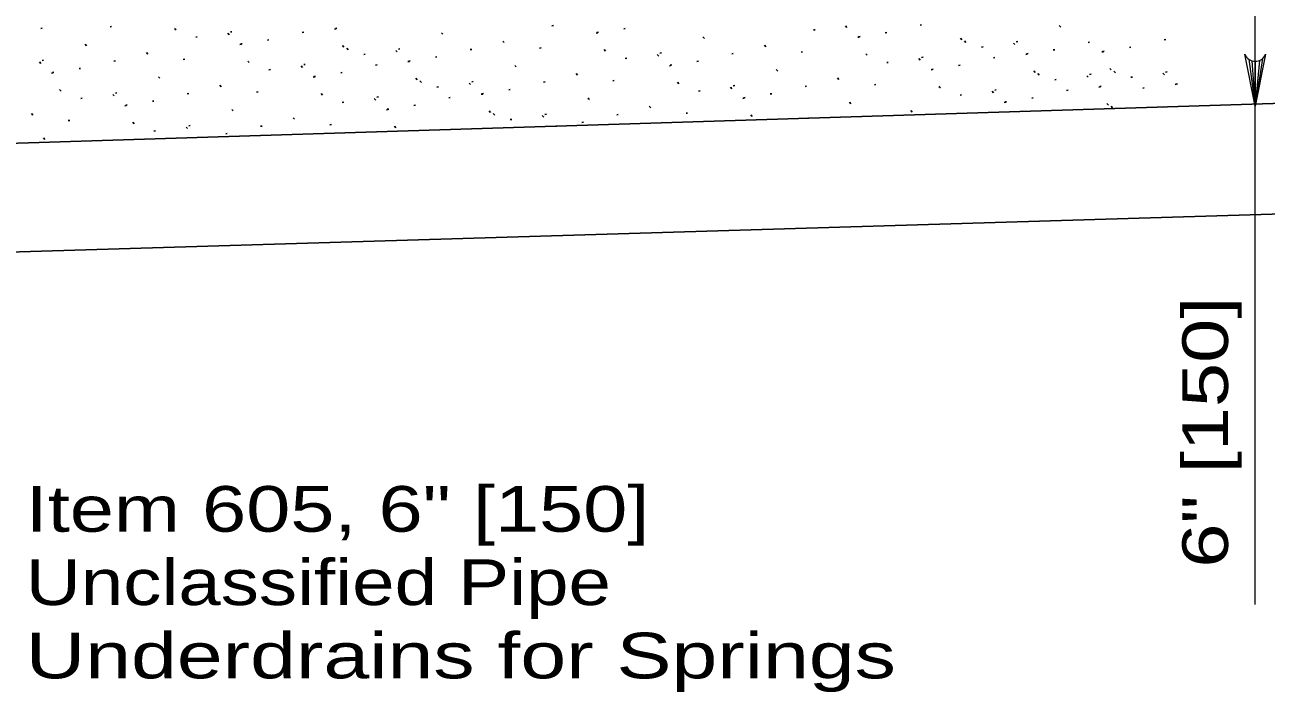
# Model space of a CAD drawing. Extents: x 1083.1 to 1117.1, y 697.4 to 741.4.
# Drawn here: x 1093.807 to 1098.05, y 702.6 to 704.879 of the extents above; entities that cross this region are included whole.
import ezdxf
from ezdxf.enums import TextEntityAlignment as Align

# ---------------------------------------------------------------- set-up
doc = ezdxf.new("R2010")
doc.units = 0
doc.header["$LTSCALE"] = 0.062
doc.layers.add('1', color=7, linetype='Continuous', lineweight=13)

msp = doc.modelspace()

# ---------------------------------------------------------------- linework, layer by layer
at = {"layer": '1'}
for p, q in [((1098.0125, 702.899), (1098.0125, 707.79508)), ((1097.99008, 704.76167), (1098.0125, 704.60142)), ((1098.00117, 704.75625), (1098.0125, 704.60142)), ((1098.03733, 704.76358), (1098.0125, 704.60142)), ((1098.02692, 704.75742), (1098.0125, 704.60142)), ((1098.0125, 704.75458), (1098.0125, 704.60142))]:
    msp.add_line(p, q, dxfattribs=at)
at = {"layer": '1', "lineweight": 25}
for p, q in [((1093.8615, 704.86692), (1093.86675, 704.86783)), ((1094.09842, 704.87233), (1094.10358, 704.87317)), ((1094.324, 704.86158), (1094.31917, 704.867)), ((1094.86608, 704.86475), (1094.87133, 704.86558)), ((1094.86875, 704.86675), (1094.874, 704.86758)), ((1095.60883, 704.87558), (1095.614, 704.8765)), ((1095.85392, 704.86583), (1095.85917, 704.86667)), ((1096.50275, 704.86142), (1096.50792, 704.86242)), ((1096.61717, 704.86975), (1096.61225, 704.87508)), ((1096.86692, 704.87767), (1096.87217, 704.87858)), ((1097.3475, 704.87158), (1097.34258, 704.87692)), ((1094.39125, 704.83658), (1094.39642, 704.83758)), ((1094.50567, 704.84492), (1094.50075, 704.85025)), ((1094.50992, 704.85458), (1094.51508, 704.85558)), ((1094.63633, 704.82683), (1094.64158, 704.82767)), ((1094.75542, 704.85283), (1094.76067, 704.85375)), ((1095.236, 704.84675), (1095.23108, 704.85208)), ((1095.4455, 704.81833), (1095.44075, 704.82375)), ((1095.76, 704.85067), (1095.76525, 704.8515)), ((1095.76267, 704.85267), (1095.76792, 704.8535)), ((1096.12992, 704.83267), (1096.125, 704.83792)), ((1096.65392, 704.83658), (1096.65917, 704.83742)), ((1096.65658, 704.8385), (1096.66183, 704.83933)), ((1096.74783, 704.85167), (1096.75308, 704.8525)), ((1097.00958, 704.828), (1097.00483, 704.83342)), ((1097.02375, 704.8185), (1097.01892, 704.82383)), ((1097.19125, 704.81133), (1097.18642, 704.81667)), ((1097.19558, 704.821), (1097.20075, 704.822)), ((1097.441, 704.81925), (1097.44625, 704.82017)), ((1097.70125, 704.82758), (1097.7065, 704.8285)), ((1094.01833, 704.80783), (1094.0135, 704.81308)), ((1094.22792, 704.77933), (1094.22317, 704.78475)), ((1094.54242, 704.81175), (1094.54767, 704.81258)), ((1094.54508, 704.81367), (1094.55033, 704.8145)), ((1094.89808, 704.80317), (1094.89333, 704.80858)), ((1094.91225, 704.79367), (1094.90742, 704.799)), ((1094.96542, 704.77817), (1094.97058, 704.77917)), ((1095.07975, 704.7865), (1095.07492, 704.79175)), ((1095.08408, 704.79617), (1095.08925, 704.79717)), ((1095.3295, 704.79442), (1095.33475, 704.79533)), ((1095.56642, 704.79975), (1095.57158, 704.80067)), ((1095.792, 704.789), (1095.78717, 704.79442)), ((1095.97367, 704.77233), (1095.96875, 704.77767)), ((1095.978, 704.78208), (1095.98317, 704.783)), ((1096.22342, 704.78025), (1096.22867, 704.78117)), ((1096.33942, 704.80417), (1096.33467, 704.80958)), ((1096.46033, 704.78567), (1096.4655, 704.78658)), ((1096.68592, 704.77492), (1096.68108, 704.78033)), ((1097.07692, 704.803), (1097.08208, 704.804)), ((1097.228, 704.77817), (1097.23325, 704.779)), ((1097.23067, 704.78008), (1097.23592, 704.78092)), ((1097.322, 704.79325), (1097.32717, 704.79408)), ((1097.48825, 704.7865), (1097.49342, 704.78733)), ((1097.49092, 704.78842), (1097.49608, 704.78925)), ((1097.58217, 704.80158), (1097.58742, 704.80242)), ((1093.86217, 704.7475), (1093.85725, 704.75283)), ((1093.8665, 704.75725), (1093.87158, 704.75817)), ((1094.11192, 704.75542), (1094.11717, 704.75633)), ((1094.34883, 704.76083), (1094.354, 704.76175)), ((1094.57442, 704.75008), (1094.56958, 704.7555)), ((1094.75608, 704.73342), (1094.75117, 704.73875)), ((1094.76033, 704.74308), (1094.7655, 704.74408)), ((1095.00583, 704.74133), (1095.01108, 704.74225)), ((1095.1165, 704.75325), (1095.12175, 704.75408)), ((1095.11917, 704.75525), (1095.12442, 704.75608)), ((1095.2105, 704.76842), (1095.21567, 704.76925)), ((1095.48642, 704.73525), (1095.4815, 704.74058)), ((1095.85925, 704.76408), (1095.86442, 704.765)), ((1096.01042, 704.73917), (1096.01567, 704.74)), ((1096.01308, 704.74117), (1096.01833, 704.742)), ((1096.10433, 704.75433), (1096.10958, 704.75517)), ((1096.75317, 704.74992), (1096.75833, 704.75092)), ((1096.86758, 704.75825), (1096.86267, 704.76358)), ((1096.87192, 704.76792), (1096.877, 704.76892)), ((1096.99825, 704.74017), (1097.0035, 704.741)), ((1097.11733, 704.76617), (1097.12258, 704.76708)), ((1093.89892, 704.71433), (1093.90417, 704.71517)), ((1093.90158, 704.71633), (1093.90683, 704.71717)), ((1093.99283, 704.7295), (1093.99808, 704.73033)), ((1094.26883, 704.69633), (1094.26392, 704.70167)), ((1094.64167, 704.72508), (1094.64683, 704.72608)), ((1094.79283, 704.70025), (1094.79808, 704.70108)), ((1094.7955, 704.70217), (1094.80075, 704.703)), ((1094.88675, 704.71533), (1094.892, 704.71617)), ((1095.1485, 704.69167), (1095.14375, 704.69708)), ((1095.69592, 704.70683), (1095.69117, 704.71225)), ((1095.81683, 704.68825), (1095.822, 704.68917)), ((1096.38033, 704.72117), (1096.37542, 704.72642)), ((1096.58983, 704.69267), (1096.58508, 704.69808)), ((1096.90433, 704.72508), (1096.90958, 704.72592)), ((1096.907, 704.727), (1096.91225, 704.72783)), ((1097.26, 704.7165), (1097.25525, 704.72192)), ((1097.27417, 704.707), (1097.26933, 704.71233)), ((1097.32733, 704.6915), (1097.3325, 704.6925)), ((1097.44167, 704.69983), (1097.43683, 704.70517)), ((1097.446, 704.7095), (1097.45117, 704.7105)), ((1097.52025, 704.72483), (1097.51542, 704.73025)), ((1097.53442, 704.71533), (1097.52958, 704.72067)), ((1097.5875, 704.69983), (1097.59267, 704.70083)), ((1097.70183, 704.70817), (1097.697, 704.7135)), ((1097.70617, 704.71783), (1097.71133, 704.71883)), ((1093.93092, 704.65267), (1093.92608, 704.65808)), ((1094.11692, 704.64575), (1094.12208, 704.64667)), ((1094.47833, 704.66783), (1094.47358, 704.67325)), ((1094.59925, 704.64933), (1094.60442, 704.65025)), ((1095.16267, 704.68217), (1095.15783, 704.6875)), ((1095.21583, 704.66667), (1095.221, 704.66767)), ((1095.33017, 704.675), (1095.32533, 704.68033)), ((1095.3345, 704.68467), (1095.33967, 704.68567)), ((1095.46092, 704.65692), (1095.46608, 704.65775)), ((1095.57992, 704.68292), (1095.58517, 704.68383)), ((1096.04242, 704.67758), (1096.03758, 704.68292)), ((1096.10975, 704.65258), (1096.11492, 704.6535)), ((1096.22408, 704.66083), (1096.21925, 704.66617)), ((1096.22842, 704.67058), (1096.23358, 704.6715)), ((1096.47383, 704.66875), (1096.47908, 704.66967)), ((1096.71075, 704.67417), (1096.71592, 704.67508)), ((1096.93633, 704.66342), (1096.9315, 704.66883)), ((1097.118, 704.64675), (1097.11308, 704.65208)), ((1097.12225, 704.65642), (1097.1275, 704.65742)), ((1097.36775, 704.65467), (1097.373, 704.65558)), ((1097.47842, 704.66667), (1097.48367, 704.6675)), ((1097.48117, 704.66858), (1097.48633, 704.66942)), ((1097.628, 704.663), (1097.63325, 704.66392)), ((1097.73867, 704.675), (1097.74383, 704.67583)), ((1097.74133, 704.67692), (1097.74658, 704.67775)), ((1091.7535, 704.41092), (1098.91383, 704.63642)), ((1093.99817, 704.62775), (1094.00333, 704.62867)), ((1094.11258, 704.636), (1094.10775, 704.64133)), ((1094.152, 704.60483), (1094.15725, 704.60567)), ((1094.24325, 704.618), (1094.2485, 704.61883)), ((1094.36233, 704.64392), (1094.36758, 704.64483)), ((1094.82483, 704.63858), (1094.82, 704.644)), ((1094.89208, 704.61358), (1094.89725, 704.61458)), ((1095.0065, 704.62192), (1095.00158, 704.62725)), ((1095.01075, 704.63158), (1095.016, 704.63258)), ((1095.13717, 704.60383), (1095.14242, 704.60467)), ((1095.25625, 704.62983), (1095.2615, 704.63075)), ((1095.36692, 704.64183), (1095.37217, 704.64267)), ((1095.36967, 704.64375), (1095.37483, 704.64458)), ((1095.73683, 704.62375), (1095.73192, 704.62908)), ((1096.26083, 704.62767), (1096.26608, 704.6285)), ((1096.2635, 704.62967), (1096.26875, 704.6305)), ((1096.35475, 704.64283), (1096.36, 704.64367)), ((1096.63075, 704.60967), (1096.62583, 704.615)), ((1097.00358, 704.63842), (1097.00883, 704.63942)), ((1097.15475, 704.61358), (1097.16, 704.61442)), ((1097.15742, 704.6155), (1097.16267, 704.61633)), ((1097.24867, 704.62875), (1097.25392, 704.6295)), ((1097.51042, 704.605), (1097.50567, 704.61042)), ((1093.83483, 704.5705), (1093.83008, 704.57592)), ((1094.14933, 704.60283), (1094.15458, 704.60367)), ((1094.51917, 704.58483), (1094.51433, 704.59008)), ((1095.04325, 704.58875), (1095.0485, 704.58958)), ((1095.04592, 704.59067), (1095.05117, 704.5915)), ((1095.39892, 704.58017), (1095.39417, 704.58558)), ((1095.41308, 704.57067), (1095.40825, 704.576)), ((1095.58058, 704.5635), (1095.57575, 704.56883)), ((1095.58492, 704.57317), (1095.59008, 704.57417)), ((1095.83033, 704.57142), (1095.83567, 704.57233)), ((1095.94642, 704.59533), (1095.94158, 704.60075)), ((1096.06725, 704.57683), (1096.07242, 704.57767)), ((1096.29283, 704.56608), (1096.28808, 704.5715)), ((1096.84025, 704.58117), (1096.8355, 704.58658)), ((1097.52467, 704.5955), (1097.51975, 704.60083)), ((1097.69658, 704.59808), (1097.70158, 704.599)), ((1093.95575, 704.55192), (1093.96092, 704.55283)), ((1094.18133, 704.54117), (1094.17658, 704.54658)), ((1094.363, 704.5245), (1094.35817, 704.52983)), ((1094.36733, 704.53425), (1094.3725, 704.53517)), ((1094.61275, 704.53242), (1094.618, 704.53333)), ((1094.72875, 704.55633), (1094.724, 704.56175)), ((1094.84967, 704.53783), (1094.85483, 704.53875)), ((1095.07525, 704.52708), (1095.07042, 704.5325)), ((1095.46625, 704.55517), (1095.47142, 704.55617)), ((1095.62308, 704.53275), (1095.62525, 704.53308)), ((1095.71133, 704.54542), (1095.7165, 704.54625)), ((1096.48292, 704.55983), (1096.484, 704.56)), ((1093.87575, 704.48742), (1093.87092, 704.49275)), ((1094.24867, 704.51625), (1094.25383, 704.51717)), ((1094.49367, 704.5065), (1094.49892, 704.50733)), ((1093.13575, 704.08392), (1100.04408, 704.29175))]:
    msp.add_line(p, q, dxfattribs=at)
at = {"layer": '1'}
msp.add_lwpolyline([(1098.04792, 704.77842), (1098.0125, 704.60142), (1097.97708, 704.77842)], dxfattribs=at)
msp.add_arc((1098.01248, 704.79273), 0.0382, 202.08782, 337.91395, dxfattribs=at)

# ---------------------------------------------------------------- texts
at = {"layer": '1', "width": 1.3}
msp.add_text('6" [150]', height=0.156, rotation=90, dxfattribs=at).set_placement((1097.91925, 703.48775), align=Align.CENTER)
at = {"layer": '1'}
for s, width, p in [('Item 605, 6" [150]', 1.3, (1093.81025, 703.14767)), ('Unclassified Pipe', 1.25, (1093.81025, 702.89725)), ('Underdrains for Springs', 1.35, (1093.81025, 702.64683))]:
    msp.add_text(s, height=0.156, dxfattribs=dict(at, width=width)).set_placement(p)

doc.saveas('drawing.dxf')
